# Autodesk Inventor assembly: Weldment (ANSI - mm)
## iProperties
Length Units: 11269
Angle Units: 11283
Time Units: 11279
Mass Units: 11290
Length Display Precision: 3
Angle Display Precision: 2
Part Number: Weldment (ANSI - mm)
Document SubType Name: Weldment
Created: 2002-06
Designer: smithga
Part Number: chapter 8a
Created: 2002-11
Designer: Elise Moss
Control State: 0
Master: False
Shininess: 64.0
Angle Units: 11279
Time Units: 11290
Mass Units: 11283
Compacted: True
Density: 0.0
Volumn: 0.0
Area: 0.0
PropertySet Name: Model Information
Author: Elise Moss
